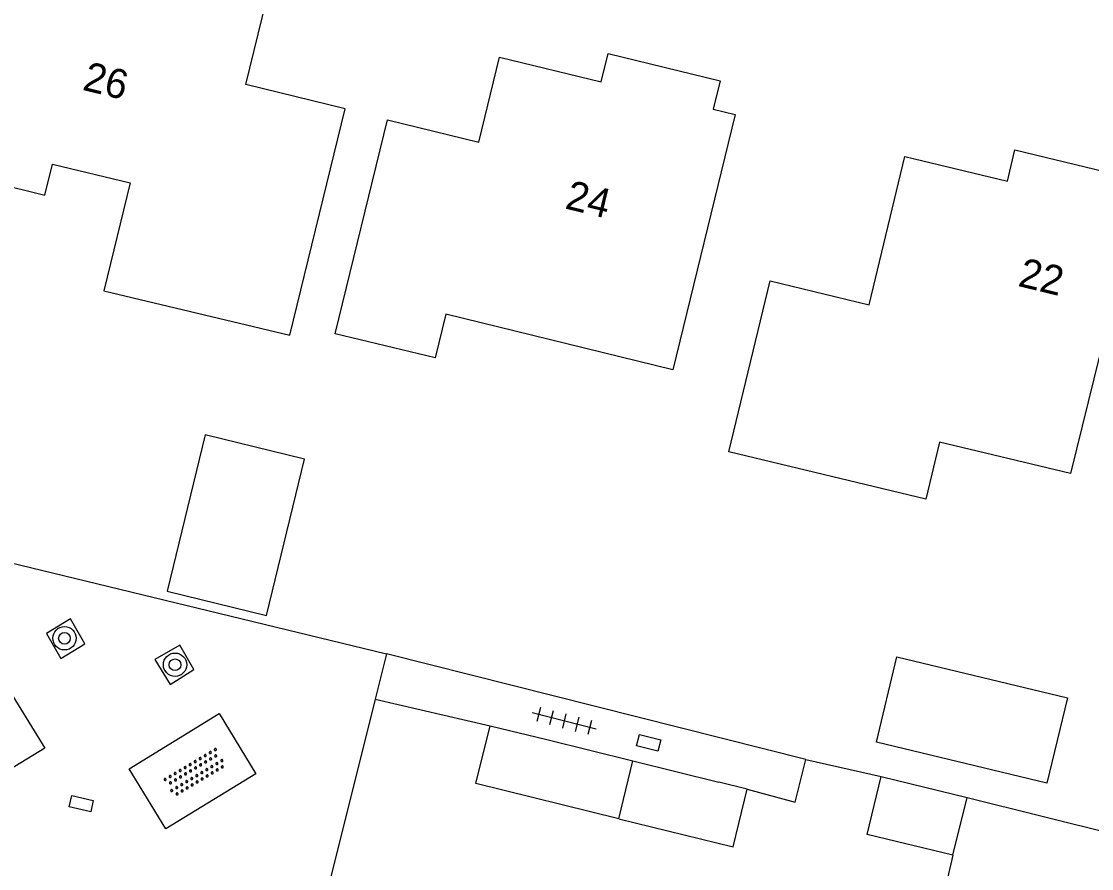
# Model space of a CAD drawing. Extents: x 125000 to 129004, y 397500 to 399008.
# Drawn here: x 126229.84 to 126266.44, y 398190.63 to 398219.6 of the extents above; entities that cross this region are included whole.
import ezdxf

# ---------------------------------------------------------------- set-up
doc = ezdxf.new("R2010")
doc.units = 0
for name, color, linetype in [('gg-afsc-erfafscheiding', 7, 'Continuous'), ('gg-afsc-hekwerk', 7, 'Continuous'), ('gg-anno-huisnummerreeks BGT', 7, 'Continuous'), ('gg-bbg-bijgebouw', 7, 'Continuous'), ('gg-bbg-gedigitaliseerde bijgebouw', 7, 'Continuous'), ('gg-bbg-hoofdgebouw', 7, 'Continuous'), ('gg-bbg-luifel en loopbrug', 7, 'Continuous'), ('gg-bbg-tussenscheiding', 7, 'Continuous'), ('gg-knt-verharding', 7, 'Continuous'), ('gt-grn-weggrens', 7, 'Continuous'), ('gt-symb-boom', 7, 'Continuous'), ('gt-symb-kolk center center', 7, 'Continuous'), ('gt-symb-overige verharding', 7, 'Continuous'), ('gt-symb-tegel verharding', 7, 'Continuous')]:
    doc.layers.add(name, color=color, linetype=linetype)

# ---------------------------------------------------------------- blocks, each defined once
blk = doc.blocks.new('gt0-BOOM')
at = {"layer": 'gt-symb-boom'}
for radius in [0.4, 0.2]:
    blk.add_circle((0, 0), radius, dxfattribs=at)
blk = doc.blocks.new('gt0-KOLKCC')
at = {"layer": 'gt-symb-kolk center center'}
blk.add_lwpolyline([(-0.375, 0.2), (0.375, 0.2), (0.375, -0.2), (-0.375, -0.2)], close=True, dxfattribs=at)
blk = doc.blocks.new('gt0-OVH')
at = {"layer": 'gt-symb-overige verharding'}
for points in [[(-0.972, 0.298), (-0.967, 0.308), (-0.965, 0.319), (-0.966, 0.33), (-0.971, 0.34), (-0.978, 0.348), (-0.988, 0.353), (-0.999, 0.355), (-1.01, 0.354), (-1.02, 0.349), (-1.028, 0.342), (-1.033, 0.332), (-1.035, 0.321), (-1.034, 0.31), (-1.029, 0.3), (-1.022, 0.292), (-1.012, 0.287), (-1.001, 0.285), (-0.99, 0.286), (-0.98, 0.291)], [(-0.872, 0.106), (-0.867, 0.116), (-0.865, 0.126), (-0.866, 0.137), (-0.871, 0.147), (-0.878, 0.156), (-0.888, 0.161), (-0.899, 0.163), (-0.91, 0.162), (-0.92, 0.157), (-0.928, 0.15), (-0.933, 0.14), (-0.935, 0.129), (-0.934, 0.118), (-0.929, 0.108), (-0.922, 0.1), (-0.912, 0.095), (-0.901, 0.092), (-0.89, 0.094), (-0.88, 0.098)], [(-0.772, 0.298), (-0.767, 0.308), (-0.765, 0.319), (-0.766, 0.33), (-0.771, 0.34), (-0.778, 0.348), (-0.788, 0.353), (-0.799, 0.355), (-0.81, 0.354), (-0.82, 0.349), (-0.828, 0.342), (-0.833, 0.332), (-0.835, 0.321), (-0.834, 0.31), (-0.829, 0.3), (-0.822, 0.292), (-0.812, 0.287), (-0.801, 0.285), (-0.79, 0.286), (-0.78, 0.291)], [(-0.672, 0.106), (-0.667, 0.116), (-0.665, 0.126), (-0.666, 0.137), (-0.671, 0.147), (-0.678, 0.156), (-0.688, 0.161), (-0.699, 0.163), (-0.71, 0.162), (-0.72, 0.157), (-0.728, 0.15), (-0.733, 0.14), (-0.735, 0.129), (-0.734, 0.118), (-0.729, 0.108), (-0.722, 0.1), (-0.712, 0.095), (-0.701, 0.092), (-0.69, 0.094), (-0.68, 0.098)], [(-0.572, 0.298), (-0.567, 0.308), (-0.565, 0.319), (-0.566, 0.33), (-0.571, 0.34), (-0.578, 0.348), (-0.588, 0.353), (-0.599, 0.355), (-0.61, 0.354), (-0.62, 0.349), (-0.628, 0.342), (-0.633, 0.332), (-0.635, 0.321), (-0.634, 0.31), (-0.629, 0.3), (-0.622, 0.292), (-0.612, 0.287), (-0.601, 0.285), (-0.59, 0.286), (-0.58, 0.291)], [(-0.472, 0.106), (-0.467, 0.116), (-0.465, 0.126), (-0.466, 0.137), (-0.471, 0.147), (-0.478, 0.156), (-0.488, 0.161), (-0.499, 0.163), (-0.51, 0.162), (-0.52, 0.157), (-0.528, 0.15), (-0.533, 0.14), (-0.535, 0.129), (-0.534, 0.118), (-0.529, 0.108), (-0.522, 0.1), (-0.512, 0.095), (-0.501, 0.092), (-0.49, 0.094), (-0.48, 0.098)], [(-0.372, 0.298), (-0.367, 0.308), (-0.365, 0.319), (-0.366, 0.33), (-0.371, 0.34), (-0.378, 0.348), (-0.388, 0.353), (-0.399, 0.355), (-0.41, 0.354), (-0.42, 0.349), (-0.428, 0.342), (-0.433, 0.332), (-0.435, 0.321), (-0.434, 0.31), (-0.429, 0.3), (-0.422, 0.292), (-0.412, 0.287), (-0.401, 0.285), (-0.39, 0.286), (-0.38, 0.291)], [(-0.272, 0.106), (-0.267, 0.116), (-0.265, 0.126), (-0.266, 0.137), (-0.271, 0.147), (-0.278, 0.156), (-0.288, 0.161), (-0.299, 0.163), (-0.31, 0.162), (-0.32, 0.157), (-0.328, 0.15), (-0.333, 0.14), (-0.335, 0.129), (-0.334, 0.118), (-0.329, 0.108), (-0.322, 0.1), (-0.312, 0.095), (-0.301, 0.092), (-0.29, 0.094), (-0.28, 0.098)], [(-0.172, 0.298), (-0.167, 0.308), (-0.165, 0.319), (-0.166, 0.33), (-0.171, 0.34), (-0.178, 0.348), (-0.188, 0.353), (-0.199, 0.355), (-0.21, 0.354), (-0.22, 0.349), (-0.228, 0.342), (-0.233, 0.332), (-0.235, 0.321), (-0.234, 0.31), (-0.229, 0.3), (-0.222, 0.292), (-0.212, 0.287), (-0.201, 0.285), (-0.19, 0.286), (-0.18, 0.291)], [(-0.072, 0.106), (-0.067, 0.116), (-0.065, 0.126), (-0.066, 0.137), (-0.071, 0.147), (-0.078, 0.156), (-0.088, 0.161), (-0.099, 0.163), (-0.11, 0.162), (-0.12, 0.157), (-0.128, 0.15), (-0.133, 0.14), (-0.135, 0.129), (-0.134, 0.118), (-0.129, 0.108), (-0.122, 0.1), (-0.112, 0.095), (-0.101, 0.092), (-0.09, 0.094), (-0.08, 0.098)], [(0.028, 0.298), (0.033, 0.308), (0.035, 0.319), (0.034, 0.33), (0.029, 0.34), (0.022, 0.348), (0.012, 0.353), (0.001, 0.355), (-0.01, 0.354), (-0.02, 0.349), (-0.028, 0.342), (-0.033, 0.332), (-0.035, 0.321), (-0.034, 0.31), (-0.029, 0.3), (-0.022, 0.292), (-0.012, 0.287), (-0.001, 0.285), (0.01, 0.286), (0.02, 0.291)], [(0.128, 0.106), (0.133, 0.116), (0.135, 0.126), (0.134, 0.137), (0.129, 0.147), (0.122, 0.156), (0.112, 0.161), (0.101, 0.163), (0.09, 0.162), (0.08, 0.157), (0.072, 0.15), (0.067, 0.14), (0.065, 0.129), (0.066, 0.118), (0.071, 0.108), (0.078, 0.1), (0.088, 0.095), (0.099, 0.092), (0.11, 0.094), (0.12, 0.098)], [(0.228, 0.298), (0.233, 0.308), (0.235, 0.319), (0.234, 0.33), (0.229, 0.34), (0.222, 0.348), (0.212, 0.353), (0.201, 0.355), (0.19, 0.354), (0.18, 0.349), (0.172, 0.342), (0.167, 0.332), (0.165, 0.321), (0.166, 0.31), (0.171, 0.3), (0.178, 0.292), (0.188, 0.287), (0.199, 0.285), (0.21, 0.286), (0.22, 0.291)], [(0.328, 0.106), (0.333, 0.116), (0.335, 0.126), (0.334, 0.137), (0.329, 0.147), (0.322, 0.156), (0.312, 0.161), (0.301, 0.163), (0.29, 0.162), (0.28, 0.157), (0.272, 0.15), (0.267, 0.14), (0.265, 0.129), (0.266, 0.118), (0.271, 0.108), (0.278, 0.1), (0.288, 0.095), (0.299, 0.092), (0.31, 0.094), (0.32, 0.098)], [(0.428, 0.298), (0.433, 0.308), (0.435, 0.319), (0.434, 0.33), (0.429, 0.34), (0.422, 0.348), (0.412, 0.353), (0.401, 0.355), (0.39, 0.354), (0.38, 0.349), (0.372, 0.342), (0.367, 0.332), (0.365, 0.321), (0.366, 0.31), (0.371, 0.3), (0.378, 0.292), (0.388, 0.287), (0.399, 0.285), (0.41, 0.286), (0.42, 0.291)], [(0.528, 0.106), (0.533, 0.116), (0.535, 0.126), (0.534, 0.137), (0.529, 0.147), (0.522, 0.156), (0.512, 0.161), (0.501, 0.163), (0.49, 0.162), (0.48, 0.157), (0.472, 0.15), (0.467, 0.14), (0.465, 0.129), (0.466, 0.118), (0.471, 0.108), (0.478, 0.1), (0.488, 0.095), (0.499, 0.092), (0.51, 0.094), (0.52, 0.098)], [(0.628, 0.298), (0.633, 0.308), (0.635, 0.319), (0.634, 0.33), (0.629, 0.34), (0.622, 0.348), (0.612, 0.353), (0.601, 0.355), (0.59, 0.354), (0.58, 0.349), (0.572, 0.342), (0.567, 0.332), (0.565, 0.321), (0.566, 0.31), (0.571, 0.3), (0.578, 0.292), (0.588, 0.287), (0.599, 0.285), (0.61, 0.286), (0.62, 0.291)], [(0.728, 0.106), (0.733, 0.116), (0.735, 0.126), (0.734, 0.137), (0.729, 0.147), (0.722, 0.156), (0.712, 0.161), (0.701, 0.163), (0.69, 0.162), (0.68, 0.157), (0.672, 0.15), (0.667, 0.14), (0.665, 0.129), (0.666, 0.118), (0.671, 0.108), (0.678, 0.1), (0.688, 0.095), (0.699, 0.092), (0.71, 0.094), (0.72, 0.098)], [(0.828, 0.298), (0.833, 0.308), (0.835, 0.319), (0.834, 0.33), (0.829, 0.34), (0.822, 0.348), (0.812, 0.353), (0.801, 0.355), (0.79, 0.354), (0.78, 0.349), (0.772, 0.342), (0.767, 0.332), (0.765, 0.321), (0.766, 0.31), (0.771, 0.3), (0.778, 0.292), (0.788, 0.287), (0.799, 0.285), (0.81, 0.286), (0.82, 0.291)], [(0.928, 0.106), (0.933, 0.116), (0.935, 0.126), (0.934, 0.137), (0.929, 0.147), (0.922, 0.156), (0.912, 0.161), (0.901, 0.163), (0.89, 0.162), (0.88, 0.157), (0.872, 0.15), (0.867, 0.14), (0.865, 0.129), (0.866, 0.118), (0.871, 0.108), (0.878, 0.1), (0.888, 0.095), (0.899, 0.092), (0.91, 0.094), (0.92, 0.098)], [(1.028, 0.298), (1.033, 0.308), (1.035, 0.319), (1.034, 0.33), (1.029, 0.34), (1.022, 0.348), (1.012, 0.353), (1.001, 0.355), (0.99, 0.354), (0.98, 0.349), (0.972, 0.342), (0.967, 0.332), (0.965, 0.321), (0.966, 0.31), (0.971, 0.3), (0.978, 0.292), (0.988, 0.287), (0.999, 0.285), (1.01, 0.286), (1.02, 0.291)], [(-0.972, -0.142), (-0.967, -0.132), (-0.965, -0.121), (-0.966, -0.11), (-0.971, -0.1), (-0.978, -0.092), (-0.988, -0.087), (-0.999, -0.085), (-1.01, -0.086), (-1.02, -0.091), (-1.028, -0.098), (-1.033, -0.108), (-1.035, -0.119), (-1.034, -0.13), (-1.029, -0.14), (-1.022, -0.148), (-1.012, -0.153), (-1.001, -0.155), (-0.99, -0.154), (-0.98, -0.149)], [(-0.872, -0.334), (-0.867, -0.324), (-0.865, -0.314), (-0.866, -0.303), (-0.871, -0.293), (-0.878, -0.284), (-0.888, -0.279), (-0.899, -0.277), (-0.91, -0.278), (-0.92, -0.283), (-0.928, -0.29), (-0.933, -0.3), (-0.935, -0.311), (-0.934, -0.322), (-0.929, -0.332), (-0.922, -0.34), (-0.912, -0.345), (-0.901, -0.348), (-0.89, -0.346), (-0.88, -0.342)], [(-0.772, -0.142), (-0.767, -0.132), (-0.765, -0.121), (-0.766, -0.11), (-0.771, -0.1), (-0.778, -0.092), (-0.788, -0.087), (-0.799, -0.085), (-0.81, -0.086), (-0.82, -0.091), (-0.828, -0.098), (-0.833, -0.108), (-0.835, -0.119), (-0.834, -0.13), (-0.829, -0.14), (-0.822, -0.148), (-0.812, -0.153), (-0.801, -0.155), (-0.79, -0.154), (-0.78, -0.149)], [(-0.672, -0.334), (-0.667, -0.324), (-0.665, -0.314), (-0.666, -0.303), (-0.671, -0.293), (-0.678, -0.284), (-0.688, -0.279), (-0.699, -0.277), (-0.71, -0.278), (-0.72, -0.283), (-0.728, -0.29), (-0.733, -0.3), (-0.735, -0.311), (-0.734, -0.322), (-0.729, -0.332), (-0.722, -0.34), (-0.712, -0.345), (-0.701, -0.348), (-0.69, -0.346), (-0.68, -0.342)], [(-0.572, -0.142), (-0.567, -0.132), (-0.565, -0.121), (-0.566, -0.11), (-0.571, -0.1), (-0.578, -0.092), (-0.588, -0.087), (-0.599, -0.085), (-0.61, -0.086), (-0.62, -0.091), (-0.628, -0.098), (-0.633, -0.108), (-0.635, -0.119), (-0.634, -0.13), (-0.629, -0.14), (-0.622, -0.148), (-0.612, -0.153), (-0.601, -0.155), (-0.59, -0.154), (-0.58, -0.149)], [(-0.472, -0.334), (-0.467, -0.324), (-0.465, -0.314), (-0.466, -0.303), (-0.471, -0.293), (-0.478, -0.284), (-0.488, -0.279), (-0.499, -0.277), (-0.51, -0.278), (-0.52, -0.283), (-0.528, -0.29), (-0.533, -0.3), (-0.535, -0.311), (-0.534, -0.322), (-0.529, -0.332), (-0.522, -0.34), (-0.512, -0.345), (-0.501, -0.348), (-0.49, -0.346), (-0.48, -0.342)], [(-0.372, -0.142), (-0.367, -0.132), (-0.365, -0.121), (-0.366, -0.11), (-0.371, -0.1), (-0.378, -0.092), (-0.388, -0.087), (-0.399, -0.085), (-0.41, -0.086), (-0.42, -0.091), (-0.428, -0.098), (-0.433, -0.108), (-0.435, -0.119), (-0.434, -0.13), (-0.429, -0.14), (-0.422, -0.148), (-0.412, -0.153), (-0.401, -0.155), (-0.39, -0.154), (-0.38, -0.149)], [(-0.272, -0.334), (-0.267, -0.324), (-0.265, -0.314), (-0.266, -0.303), (-0.271, -0.293), (-0.278, -0.284), (-0.288, -0.279), (-0.299, -0.277), (-0.31, -0.278), (-0.32, -0.283), (-0.328, -0.29), (-0.333, -0.3), (-0.335, -0.311), (-0.334, -0.322), (-0.329, -0.332), (-0.322, -0.34), (-0.312, -0.345), (-0.301, -0.348), (-0.29, -0.346), (-0.28, -0.342)], [(-0.172, -0.142), (-0.167, -0.132), (-0.165, -0.121), (-0.166, -0.11), (-0.171, -0.1), (-0.178, -0.092), (-0.188, -0.087), (-0.199, -0.085), (-0.21, -0.086), (-0.22, -0.091), (-0.228, -0.098), (-0.233, -0.108), (-0.235, -0.119), (-0.234, -0.13), (-0.229, -0.14), (-0.222, -0.148), (-0.212, -0.153), (-0.201, -0.155), (-0.19, -0.154), (-0.18, -0.149)], [(-0.072, -0.334), (-0.067, -0.324), (-0.065, -0.314), (-0.066, -0.303), (-0.071, -0.293), (-0.078, -0.284), (-0.088, -0.279), (-0.099, -0.277), (-0.11, -0.278), (-0.12, -0.283), (-0.128, -0.29), (-0.133, -0.3), (-0.135, -0.311), (-0.134, -0.322), (-0.129, -0.332), (-0.122, -0.34), (-0.112, -0.345), (-0.101, -0.348), (-0.09, -0.346), (-0.08, -0.342)], [(0.028, -0.142), (0.033, -0.132), (0.035, -0.121), (0.034, -0.11), (0.029, -0.1), (0.022, -0.092), (0.012, -0.087), (0.001, -0.085), (-0.01, -0.086), (-0.02, -0.091), (-0.028, -0.098), (-0.033, -0.108), (-0.035, -0.119), (-0.034, -0.13), (-0.029, -0.14), (-0.022, -0.148), (-0.012, -0.153), (-0.001, -0.155), (0.01, -0.154), (0.02, -0.149)], [(0.128, -0.334), (0.133, -0.324), (0.135, -0.314), (0.134, -0.303), (0.129, -0.293), (0.122, -0.284), (0.112, -0.279), (0.101, -0.277), (0.09, -0.278), (0.08, -0.283), (0.072, -0.29), (0.067, -0.3), (0.065, -0.311), (0.066, -0.322), (0.071, -0.332), (0.078, -0.34), (0.088, -0.345), (0.099, -0.348), (0.11, -0.346), (0.12, -0.342)], [(0.228, -0.142), (0.233, -0.132), (0.235, -0.121), (0.234, -0.11), (0.229, -0.1), (0.222, -0.092), (0.212, -0.087), (0.201, -0.085), (0.19, -0.086), (0.18, -0.091), (0.172, -0.098), (0.167, -0.108), (0.165, -0.119), (0.166, -0.13), (0.171, -0.14), (0.178, -0.148), (0.188, -0.153), (0.199, -0.155), (0.21, -0.154), (0.22, -0.149)], [(0.328, -0.334), (0.333, -0.324), (0.335, -0.314), (0.334, -0.303), (0.329, -0.293), (0.322, -0.284), (0.312, -0.279), (0.301, -0.277), (0.29, -0.278), (0.28, -0.283), (0.272, -0.29), (0.267, -0.3), (0.265, -0.311), (0.266, -0.322), (0.271, -0.332), (0.278, -0.34), (0.288, -0.345), (0.299, -0.348), (0.31, -0.346), (0.32, -0.342)], [(0.428, -0.142), (0.433, -0.132), (0.435, -0.121), (0.434, -0.11), (0.429, -0.1), (0.422, -0.092), (0.412, -0.087), (0.401, -0.085), (0.39, -0.086), (0.38, -0.091), (0.372, -0.098), (0.367, -0.108), (0.365, -0.119), (0.366, -0.13), (0.371, -0.14), (0.378, -0.148), (0.388, -0.153), (0.399, -0.155), (0.41, -0.154), (0.42, -0.149)], [(0.528, -0.334), (0.533, -0.324), (0.535, -0.314), (0.534, -0.303), (0.529, -0.293), (0.522, -0.284), (0.512, -0.279), (0.501, -0.277), (0.49, -0.278), (0.48, -0.283), (0.472, -0.29), (0.467, -0.3), (0.465, -0.311), (0.466, -0.322), (0.471, -0.332), (0.478, -0.34), (0.488, -0.345), (0.499, -0.348), (0.51, -0.346), (0.52, -0.342)], [(0.628, -0.142), (0.633, -0.132), (0.635, -0.121), (0.634, -0.11), (0.629, -0.1), (0.622, -0.092), (0.612, -0.087), (0.601, -0.085), (0.59, -0.086), (0.58, -0.091), (0.572, -0.098), (0.567, -0.108), (0.565, -0.119), (0.566, -0.13), (0.571, -0.14), (0.578, -0.148), (0.588, -0.153), (0.599, -0.155), (0.61, -0.154), (0.62, -0.149)], [(0.728, -0.334), (0.733, -0.324), (0.735, -0.314), (0.734, -0.303), (0.729, -0.293), (0.722, -0.284), (0.712, -0.279), (0.701, -0.277), (0.69, -0.278), (0.68, -0.283), (0.672, -0.29), (0.667, -0.3), (0.665, -0.311), (0.666, -0.322), (0.671, -0.332), (0.678, -0.34), (0.688, -0.345), (0.699, -0.348), (0.71, -0.346), (0.72, -0.342)], [(0.828, -0.142), (0.833, -0.132), (0.835, -0.121), (0.834, -0.11), (0.829, -0.1), (0.822, -0.092), (0.812, -0.087), (0.801, -0.085), (0.79, -0.086), (0.78, -0.091), (0.772, -0.098), (0.767, -0.108), (0.765, -0.119), (0.766, -0.13), (0.771, -0.14), (0.778, -0.148), (0.788, -0.153), (0.799, -0.155), (0.81, -0.154), (0.82, -0.149)], [(0.928, -0.334), (0.933, -0.324), (0.935, -0.314), (0.934, -0.303), (0.929, -0.293), (0.922, -0.284), (0.912, -0.279), (0.901, -0.277), (0.89, -0.278), (0.88, -0.283), (0.872, -0.29), (0.867, -0.3), (0.865, -0.311), (0.866, -0.322), (0.871, -0.332), (0.878, -0.34), (0.888, -0.345), (0.899, -0.348), (0.91, -0.346), (0.92, -0.342)], [(1.028, -0.142), (1.033, -0.132), (1.035, -0.121), (1.034, -0.11), (1.029, -0.1), (1.022, -0.092), (1.012, -0.087), (1.001, -0.085), (0.99, -0.086), (0.98, -0.091), (0.972, -0.098), (0.967, -0.108), (0.965, -0.119), (0.966, -0.13), (0.971, -0.14), (0.978, -0.148), (0.988, -0.153), (0.999, -0.155), (1.01, -0.154), (1.02, -0.149)]]:
    blk.add_lwpolyline(points, close=True, dxfattribs=at)
blk = doc.blocks.new('gt0-TEG1')
at = {"layer": 'gt-symb-tegel verharding'}
for p, q in [((-1.125, 0), (1.125, 0)), ((-0.9, -0.25), (-0.9, 0.25)), ((-0.45, -0.25), (-0.45, 0.25)), ((0, -0.25), (0, 0.25)), ((0.45, -0.25), (0.45, 0.25)), ((0.9, -0.25), (0.9, 0.25))]:
    blk.add_line(p, q, dxfattribs=at)

msp = doc.modelspace()

# ---------------------------------------------------------------- linework, layer by layer
at = {"layer": 'gg-afsc-erfafscheiding'}
for p, q in [((126241.941, 398196.427), (126245.873, 398195.519)), ((126256.67, 398194.366), (126259.249, 398193.782))]:
    msp.add_line(p, q, dxfattribs=at)
msp.add_lwpolyline([(126254.668, 398193.353), (126256.302, 398192.904), (126256.67, 398194.366)], dxfattribs=at)
at = {"layer": 'gg-afsc-hekwerk'}
msp.add_line((126241.941, 398196.427), (126239.671, 398187.328), dxfattribs=at)
at = {"layer": 'gg-bbg-bijgebouw'}
msp.add_line((126259.249, 398193.782), (126262.184, 398193.068), dxfattribs=at)
msp.add_lwpolyline([(126261.702, 398191.086), (126258.767, 398191.8), (126259.249, 398193.782)], dxfattribs=at)
at = {"layer": 'gg-bbg-gedigitaliseerde bijgebouw'}
for p, q in [((126245.873, 398195.519), (126247.815, 398195.041)), ((126247.815, 398195.041), (126250.756, 398194.317)), ((126250.756, 398194.317), (126253.697, 398193.592)), ((126254.668, 398193.353), (126253.697, 398193.592)), ((126262.184, 398193.068), (126267.679, 398191.701))]:
    msp.add_line(p, q, dxfattribs=at)
for points in [[(126250.268, 398192.335), (126245.385, 398193.539), (126245.873, 398195.519)], [(126250.268, 398192.335), (126254.18, 398191.372), (126254.668, 398193.353)], [(126261.702, 398191.086), (126261.512, 398190.309), (126267.011, 398188.966), (126267.318, 398190.224)]]:
    msp.add_lwpolyline(points, dxfattribs=at)
at = {"layer": 'gg-bbg-hoofdgebouw'}
for points in [[(126225.583, 398214.913), (126230.636, 398213.654), (126230.908, 398214.721), (126233.558, 398214.078), (126232.654, 398210.386), (126239.025, 398208.873), (126240.915, 398216.612), (126237.518, 398217.445), (126238.222, 398220.338), (126231.281, 398222.053), (126231.507, 398223.014), (126228.314, 398223.791), (126228.078, 398222.819), (126227.544, 398222.949), (126225.583, 398214.913)], [(126242.361, 398216.234), (126245.486, 398215.471), (126246.197, 398218.382), (126249.672, 398217.532), (126249.91, 398218.505), (126253.736, 398217.569), (126253.497, 398216.595), (126254.247, 398216.412), (126252.119, 398207.684), (126244.356, 398209.591), (126243.995, 398208.094), (126240.569, 398208.92), (126242.361, 398216.234)], [(126260.054, 398214.985), (126263.566, 398214.136), (126263.824, 398215.205), (126267.59, 398214.293), (126267.331, 398213.217), (126267.921, 398213.061), (126265.721, 398204.136), (126261.243, 398205.214), (126260.773, 398203.262), (126254.041, 398204.882), (126255.448, 398210.726), (126258.833, 398209.912), (126260.054, 398214.985)]]:
    msp.add_lwpolyline(points, dxfattribs=at)
at = {"layer": 'gg-bbg-luifel en loopbrug'}
for points in [[(126238.221, 398199.29), (126239.524, 398204.634), (126236.123, 398205.463), (126234.82, 398200.12), (126238.221, 398199.29)], [(126264.916, 398193.552), (126259.082, 398194.956), (126259.784, 398197.872), (126265.618, 398196.468), (126264.916, 398193.552)]]:
    msp.add_lwpolyline(points, dxfattribs=at)
at = {"layer": 'gg-bbg-tussenscheiding'}
for p, q in [((126250.268, 398192.335), (126250.756, 398194.317)), ((126261.702, 398191.086), (126262.184, 398193.068))]:
    msp.add_line(p, q, dxfattribs=at)
at = {"layer": 'gg-knt-verharding'}
for p in [(126224.988, 398202.18), (126256.67, 398194.366)]:
    msp.add_line(p, (126242.332, 398197.979), dxfattribs=at)
for points in [[(126230.697, 398198.666), (126231.188, 398197.819), (126232.014, 398198.322), (126231.523, 398199.17), (126230.697, 398198.666)], [(126226.26, 398192.085), (126224.246, 398195.388), (126228.588, 398198.065), (126230.636, 398194.747), (126226.26, 398192.085)], [(126234.4, 398197.778), (126234.922, 398196.932), (126235.732, 398197.435), (126235.259, 398198.269), (126234.4, 398197.778)], [(126233.526, 398194.041), (126236.601, 398195.938), (126237.855, 398193.877), (126234.779, 398191.993), (126233.526, 398194.041)]]:
    msp.add_lwpolyline(points, dxfattribs=at)
at = {"layer": 'gt-grn-weggrens'}
msp.add_line((126242.332, 398197.979), (126241.941, 398196.427), dxfattribs=at)

# ---------------------------------------------------------------- block references
at = {"layer": 'gt-symb-boom'}
for p in [(126231.312, 398198.507), (126235.094, 398197.603)]:
    msp.add_blockref('gt0-BOOM', p, dxfattribs=at)
at = {"layer": 'gt-symb-kolk center center'}
for p, rotation in [((126251.294, 398194.936), 166.1165819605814), ((126231.887, 398192.854), -12.771242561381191)]:
    msp.add_blockref('gt0-KOLKCC', p, dxfattribs=dict(at, rotation=rotation))
at = {"layer": 'gt-symb-overige verharding', "rotation": 30.796713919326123}
msp.add_blockref('gt0-OVH', (126235.777, 398193.914), dxfattribs=at)
at = {"layer": 'gt-symb-tegel verharding', "rotation": 165.6997225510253}
msp.add_blockref('gt0-TEG1', (126248.404, 398195.678), dxfattribs=at)

# ---------------------------------------------------------------- texts
at = {"layer": 'gg-anno-huisnummerreeks BGT'}
for s, rotation, p in [('26', 346.1, (126231.894, 398217.267)), ('24', 346.2, (126248.397, 398213.211)), ('22', 346.4, (126263.894, 398210.558))]:
    msp.add_text(s, height=1, rotation=rotation, dxfattribs=at).set_placement(p)

doc.saveas('drawing.dxf')
